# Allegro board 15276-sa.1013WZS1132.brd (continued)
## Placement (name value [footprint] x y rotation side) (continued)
PC4516  SCD1U16V2KX-3GP  [C402H22]  41 26.81 90 bottom
PC4521  SC18P50V2JN-1-GP  [C402H22]  42.4 58.3 0 top
PC4523  SCD1U50V3KX-L-GP  [C603H36]  34.02 47.64 90 top
PC4524  SCD1U50V3KX-L-GP  [C603H36]  39 50.3 0 top
PC4525  SCD1U50V3KX-L-GP  [C603H36]  45.19 47.25 270 top
PC4528  SC10U25V5KX-GP  [C805H56]  40.37 58.68 0 bottom
PC4529  SC10U25V5KX-GP  [C805H56]  40.55 50.05 0 top
PC4530  SC10U25V5KX-GP  [C805H56]  45.19 48.91 90 bottom
PC4601  SC1KP50V2KX-1GP  [C402H22]  124.8 143.98 180 top
PC4602  SC1U25V3KX-1-GP  [C603H36]  118.6 145.93 180 top
PC4603  SC3300P50V2KX-1GP  [C402H22]  124.75 139.43 180 bottom
PC4604  SCD1U10V2KX-4GP  [C402H20]  120 142.38 180 bottom
PC4605  SC1KP50V2KX-1GP  [C402H22]  113.14 143.83 270 top
PC4606  SC1KP50V2KX-1GP  [C402H22]  125.13 137.7 90 top
PC4607  SCD1U16V2KX-3GP  [C402H22]  122.46 145.04 0 top
PC4608  SC2D2U10V3KX-1GP  [C603H36]  119.03 133.11 0 top
PC4609  SCD01U50V2KX-1GP  [C402H22]  125.2 141.51 270 bottom
PC4610  SC330P50V2KX-3GP  [C402H22]  113.16 142.2 90 bottom
PC4611  SC2200P50V2KX-2GP  [C402H22]  113.49 140.93 0 bottom
PC4612  SC10P50V2JN-4GP  [C402H22]  113.22 139.69 270 bottom
PC4613  SC470P50V2KX-3GP  [C402H22]  113.82 137.09 270 bottom
PC4614  SCD01U50V2KX-1GP  [C402H22]  115.27 145.1 90 top
PC4615  SC100P50V2JN-3GP  [C402H22]  125.58 139 0 top
PC4616  SCD01U50V2KX-1GP  [C402H22]  113.04 142.17 90 top
PC4617  SC100P50V2JN-3GP  [C402H22]  112.55 136.61 180 bottom
PC4618  SC470P50V2KX-3GP  [C402H22]  124.75 139 0 top
PC4619  SCD1U16V2KX-3GP  [C402H22]  113.14 144.64 90 top
PC4622  SC1KP50V2KX-1GP  [C402H22]  113.82 137.78 270 top
PC4623  SCD047U25V2KX-GP  [C402H22]  114.28 136.54 180 top
PC4624  SC3300P50V2KX-1GP  [C402H22]  113.6 140.12 0 top
PC4626  SC2200P50V2KX-2GP  [C402H22]  126.27 141.06 90 top
PC4627  SC10P50V2JN-4GP  [C402H22]  124.75 140.68 0 top
PC4628  SCD047U25V2KX-GP  [C402H22]  125.13 136 90 top
PC4648  SC330P50V2KX-3GP  [C402H22]  126.7 142.33 0 top
PC4660  SC1KP50V2KX-1GP  [C402H22]  120.12 147.08 90 top
PC4713  SC10U25V5KX-GP  [C805H56]  110.73 130.31 90 top
PC4715  SC10U25V5KX-GP  [C805H56]  110.73 129.12 270 bottom
PC4716  SC10U25V5KX-GP  [C805H56]  126.85 130.31 90 bottom
PC4717  SC10U25V5KX-GP  [C805H56]  126.85 128.28 90 bottom
PC4718  SC10U25V5KX-GP  [C805H56]  126.85 132.22 270 top
PC4719  SC10U25V5KX-GP  [C805H56]  110.78 127.32 270 bottom
PC4720  SCD1U50V3KX-GP  [C603H36]  110.83 127.09 90 top
PC4721  SC10U25V5KX-GP  [C805H56]  126.85 130.31 270 top
PC4722  SCD1U50V3KX-GP  [C603H36]  126.85 126.58 90 bottom
PC4734  SCD22U25V3KX-GP  [C603H40]  120.43 133.11 0 bottom
PC4736  SCD22U25V3KX-GP  [C603H40]  117.63 133.11 0 bottom
PC4742  SC1KP50V2KX-1GP  [C402H22]  111.51 123.56 0 bottom
PC4743  SC1KP50V2KX-1GP  [C402H22]  126.47 124.72 0 bottom
PC4827  SCD1U50V3KX-GP  [C603H36]  154.67 103.52 270 bottom
PC4828  SC4D7U25V5KX-GP  [C805H54]  154.67 105.17 270 bottom
PC4829  SC1U10V2KX-1GP  [C402H22]  156.45 111.77 0 bottom
PC4830  SC10U25V5KX-GP  [C805H56]  154.67 107.07 270 bottom
PC4831  SC1KP50V2KX-1GP  [C402H22]  153.4 117.87 0 bottom
PC4832  SC18P50V2JN-1-GP  [C402H22]  156.06 117.87 180 bottom
PC4833  SCD1U50V3KX-GP  [C603H36]  153.4 109.48 180 bottom
PC4834  SCD1U10V2KX-4GP  [C402H20]  150.48 79.89 90 bottom
PC4838  SC560P50V-GP  [C603]  160.38 102.75 0 bottom
PC4901  SC1U10V3KX-3GP  [C603H36]  59.8 41.92 0 top
PC4902  SCD01U16V2KX-3GP  [C402H22]  56.62 46.24 270 top
PC4903  SCD1U10V2KX-4GP  [C402H20]  56.62 47.13 270 top
PC4904  SC1U10V3KX-3GP  [C603H36]  61.83 47.76 90 bottom
PC4906  SCD1U10V2KX-5GP  [C402H22]  65.88 44.85 90 top
PC4909  SC4D7U25V5KX-GP  [C805H54]  59.29 37.27 270 top
PC4911  SC4D7U25V5KX-GP  [C805H54]  59.29 35.47 270 top
PC4912  SC10U25V5KX-GP  [C805H56]  59.29 37.25 90 bottom
PC4913  SCD1U50V3KX-GP  [C603H36]  59.29 38.82 90 top
PC4914  SC4D7U25V5KX-GP  [C805H54]  59.29 35.44 90 bottom
PC4915  SCD1U10V2KX-4GP  [C402H20]  60.31 50.3 180 top
PC4916  SC10U6D3V3MX-GP  [C603H38]  61.45 50.56 180 top
PC4917  SC10U6D3V3MX-GP  [C603H38]  62.72 50.56 180 top
PC4918  SCD22U10V2KX-1GP  [C402H22]  59.42 50.3 180 top
PC4919  SCD1U50V3KX-GP  [C603H36]  61.45 41.54 180 top
PC4920  SC4D7U6D3V3KX-GP  [C603H36]  68.43 26.05 180 top
PC4921  SCD1U10V2KX-4GP  [C402H20]  69.58 18.3 0 top
PC4922  SC330P50V2KX-3GP  [C402H22]  58.94 33.56 180 top
PC4923  SC22U6D3V5MX-2GP  [C805H58]  66.78 25.92 180 top
PC4924  SC22U6D3V5MX-2GP  [C805H58]  64.88 25.92 180 top
PC4925  SC22U6D3V5MX-2GP  [C805H58]  64.88 18.3 0 top
PC4926  SC22U6D3V5MX-2GP  [C805H58]  66.78 18.3 0 top
PC5005  SC1U10V2KX-1GP  [C402H22]  49 61.99 180 bottom
PC5010  SC10U6D3V3MX-GP  [C603H38]  63.74 68.72 0 bottom
PC5011  SC10U6D3V3MX-GP  [C603H38]  49.89 68.97 0 bottom
PC5012  SC10U6D3V3MX-GP  [C603H38]  65.01 68.72 0 bottom
PC5013  SC1U6D3V2KX-GP  [C402H22]  47.23 64.53 180 bottom
PC5014  SC22P50V2JN-4GP  [C402H22]  46.21 62.75 180 top
PC5015  SC10U6D3V3MX-GP  [C603H38]  48.5 68.97 0 bottom
PC5020  SC680P50V2KX-2GP  [C402H22]  45.32 62.75 0 top
PD4201  P6SMB27A-GP  [DO214AAAKH97]  92.62 156.25 0 bottom
PD4203  LBAV99LT1G-1-GP  [SOT23-2D4-312H44]  78.98 168.67 0 top
PD4204  PESD24VS2UT-GP  [SOT-23-10H44]  85.45 173.24 0 top
PD4302  SMF18AT1G-GP  [SOD123FLAKH40]  156.57 172.35 90 top
PD4401  SD103AWS-1-GP  [SOD323AKH42]  133.08 153.05 270 bottom
PD4404  1N4148WS-7-F-GP  [SOD323AKH42]  117.15 157.74 270 top
PG4402  GAP-CLOSE-PWR-3-GP  [GAP-CLOSE-PWR-3]  118.85 173.11 90 top
PG4403  GAP-CLOSE-PWR-3-GP  [GAP-CLOSE-PWR-3]  120.63 173.11 90 top
PG4407  GAP-CLOSE-PWR-3-GP  [GAP-CLOSE-PWR-3]  123.43 155.48 180 top
PG4408  GAP-CLOSE-PWR-3-GP  [GAP-CLOSE-PWR-3]  123.43 156.4 180 top
PG4409  GAP-CLOSE-PWR-3-GP  [GAP-CLOSE-PWR-3]  159.37 162.44 180 bottom
PG4410  GAP-CLOSE-PWR-3-GP  [GAP-CLOSE-PWR-3]  159.37 163.97 180 bottom
PG4411  GAP-CLOSE-PWR-3-GP  [GAP-CLOSE-PWR-3]  126.6 154.32 180 bottom
PG4412  GAP-CLOSE-PWR-3-GP  [GAP-CLOSE-PWR-3]  140.95 159.65 270 bottom
PG4413  GAP-CLOSE-PWR-3-GP  [GAP-CLOSE-PWR-3]  140.19 159.65 270 bottom
PG4414  GAP-CLOSE-PWR-3-GP  [GAP-CLOSE-PWR-3]  139.43 159.65 270 bottom
PG4415  GAP-CLOSE-PWR-3-GP  [GAP-CLOSE-PWR-3]  138.67 159.65 270 bottom
PG4502  GAP-CLOSE-PWR-3-GP  [GAP-CLOSE-PWR-3]  30.46 50.94 90 top
PG4503  GAP-CLOSE-PWR-3-GP  [GAP-CLOSE-PWR-3]  31.22 50.94 90 top
PG4504  GAP-CLOSE-PWR-3-GP  [GAP-CLOSE-PWR-3]  31.99 50.94 90 top
PG4505  GAP-CLOSE-PWR-3-GP  [GAP-CLOSE-PWR-3]  32.87 50.94 90 top
PG4511  GAP-CLOSE-PWR-3-GP  [GAP-CLOSE-PWR-3]  47.23 26.43 90 bottom
PG4512  GAP-CLOSE-PWR-3-GP  [GAP-CLOSE-PWR-3]  46.46 26.43 90 bottom
PG4513  GAP-CLOSE-PWR-3-GP  [GAP-CLOSE-PWR-3]  30.46 26.68 270 bottom
PG4514  GAP-CLOSE-PWR-3-GP  [GAP-CLOSE-PWR-3]  47.99 26.43 90 bottom
PG4515  GAP-CLOSE-PWR-3-GP  [GAP-CLOSE-PWR-3]  50.15 47.51 0 top
PG4516  GAP-CLOSE-PWR-3-GP  [GAP-CLOSE-PWR-3]  50.15 48.27 0 top
PG4517  GAP-CLOSE-PWR-3-GP  [GAP-CLOSE-PWR-3]  50.15 49.03 0 top
PG4518  GAP-CLOSE-PWR-3-GP  [GAP-CLOSE-PWR-3]  50.15 49.79 0 top
PG4519  GAP-CLOSE-PWR-3-GP  [GAP-CLOSE-PWR-3]  50.15 50.56 0 top
PG4520  GAP-CLOSE-PWR-3-GP  [GAP-CLOSE-PWR-3]  50.15 51.32 0 top
PG4521  GAP-CLOSE-PWR-3-GP  [GAP-CLOSE-PWR-3]  50.15 52.08 0 top
PG4522  GAP-CLOSE-PWR-3-GP  [GAP-CLOSE-PWR-3]  31.22 26.68 270 bottom
PG4523  GAP-CLOSE-PWR-3-GP  [GAP-CLOSE-PWR-3]  31.99 26.68 270 bottom
PG4524  GAP-CLOSE-PWR-3-GP  [GAP-CLOSE-PWR-3]  43.42 26.43 90 bottom
PG4525  GAP-CLOSE-PWR-3-GP  [GAP-CLOSE-PWR-3]  32.75 26.68 270 bottom
PG4526  GAP-CLOSE-PWR-3-GP  [GAP-CLOSE-PWR-3]  33.51 26.68 270 bottom
PG4527  GAP-CLOSE-PWR-3-GP  [GAP-CLOSE-PWR-3]  42.65 26.43 90 bottom
PG4528  GAP-CLOSE-PWR-3-GP  [GAP-CLOSE-PWR-3]  44.18 26.43 90 bottom
PG4529  GAP-CLOSE-PWR-3-GP  [GAP-CLOSE-PWR-3]  44.94 26.43 90 bottom
PG4530  GAP-CLOSE-PWR-3-GP  [GAP-CLOSE-PWR-3]  34.27 26.68 270 bottom
PG4531  GAP-CLOSE-PWR-3-GP  [GAP-CLOSE-PWR-3]  45.7 26.43 90 bottom
PG4535  GAP-CLOSE-PWR-3-GP  [GAP-CLOSE-PWR-3]  48.75 26.43 90 bottom
PG4537  GAP-CLOSE-PWR-6-GP  [GAP-CLOSE-PWR]  27.79 27.95 180 bottom
PG4538  GAP-CLOSE-PWR-6-GP  [GAP-CLOSE-PWR]  41.76 57.92 270 bottom
PG4543  GAP-CLOSE-PWR-6-GP  [GAP-CLOSE-PWR]  41.92 50.68 270 top
PG4547  GAP-CLOSE-PWR-6-GP  [GAP-CLOSE-PWR]  50.15 27.95 0 bottom
PG4701  GAP-CLOSE-PWR-3-GP  [GAP-CLOSE-PWR-3]  111.36 114.31 90 bottom
PG4702  GAP-CLOSE-PWR-3-GP  [GAP-CLOSE-PWR-3]  111.36 112.02 270 bottom
PG4703  GAP-CLOSE-PWR-3-GP  [GAP-CLOSE-PWR-3]  103.26 122.11 180 bottom
PG4704  GAP-CLOSE-PWR-3-GP  [GAP-CLOSE-PWR-3]  103.26 122.87 180 bottom
PG4707  GAP-CLOSE-PWR-3-GP  [GAP-CLOSE-PWR-3]  103.26 125.16 180 bottom
PG4708  GAP-CLOSE-PWR-3-GP  [GAP-CLOSE-PWR-3]  103.26 125.92 180 bottom
PG4709  GAP-CLOSE-PWR-3-GP  [GAP-CLOSE-PWR-3]  103.26 124.39 180 bottom
PG4710  GAP-CLOSE-PWR-3-GP  [GAP-CLOSE-PWR-3]  103.26 123.63 180 bottom
PG4711  GAP-CLOSE-PWR-3-GP  [GAP-CLOSE-PWR-3]  132.57 131.71 0 top
PG4712  GAP-CLOSE-PWR-3-GP  [GAP-CLOSE-PWR-3]  132.57 130.95 0 top
PG4716  GAP-CLOSE-PWR-3-GP  [GAP-CLOSE-PWR-3]  132.57 130.19 0 top
PG4717  GAP-CLOSE-PWR-3-GP  [GAP-CLOSE-PWR-3]  132.57 133.23 0 top
PG4718  GAP-CLOSE-PWR-3-GP  [GAP-CLOSE-PWR-3]  132.57 132.47 0 top
PG4719  GAP-CLOSE-PWR-3-GP  [GAP-CLOSE-PWR-3]  123.55 111.77 270 bottom
PG4720  GAP-CLOSE-PWR-3-GP  [GAP-CLOSE-PWR-3]  123.55 114.06 90 bottom
PG4824  GAP-CLOSE-PWR-3-GP  [GAP-CLOSE-PWR-3]  150.48 82.81 0 bottom
PG4825  GAP-CLOSE-PWR-3-GP  [GAP-CLOSE-PWR-3]  150.48 83.58 0 bottom
PG4826  GAP-CLOSE-PWR-3-GP  [GAP-CLOSE-PWR-3]  150.48 84.34 0 bottom
PG4827  GAP-CLOSE-PWR-3-GP  [GAP-CLOSE-PWR-3]  148.7 108.98 90 top
PG4828  GAP-CLOSE-PWR-3-GP  [GAP-CLOSE-PWR-3]  150.48 85.1 0 bottom
PG4830  GAP-CLOSE-PWR-3-GP  [GAP-CLOSE-PWR-3]  150.48 81.29 0 bottom
PG4831  GAP-CLOSE-PWR-3-GP  [GAP-CLOSE-PWR-3]  150.48 82.05 0 bottom
PG4832  GAP-CLOSE-PWR-3-GP  [GAP-CLOSE-PWR-3]  150.48 86.24 0 bottom
PG4834  GAP-CLOSE-PWR-3-GP  [GAP-CLOSE-PWR-3]  147.17 108.98 90 top
PG4837  GAP-CLOSE-PWR-3-GP  [GAP-CLOSE-PWR-3]  149.46 108.98 90 top
PG4838  GAP-CLOSE-PWR-3-GP  [GAP-CLOSE-PWR-3]  147.94 108.98 90 top
PG4901  GAP-CLOSE-PWR-3-GP  [GAP-CLOSE-PWR-3]  65.64 51.19 180 top
PG4902  GAP-CLOSE-PWR-3-GP  [GAP-CLOSE-PWR-3]  65.64 50.43 180 top
PG4903  GAP-CLOSE-PWR-3-GP  [GAP-CLOSE-PWR-3]  66.53 38.49 90 top
PG4904  GAP-CLOSE-PWR-3-GP  [GAP-CLOSE-PWR-3]  65.64 38.49 90 top
PG4905  GAP-CLOSE-PWR-3-GP  [GAP-CLOSE-PWR-3]  64.75 38.49 90 top
PG4906  GAP-CLOSE-PWR-3-GP  [GAP-CLOSE-PWR-3]  67.42 38.49 90 top
PG4907  GAP-CLOSE-PWR-3-GP  [GAP-CLOSE-PWR-3]  60.43 19.19 0 top
PG4908  GAP-CLOSE-PWR-3-GP  [GAP-CLOSE-PWR-3]  70.72 23.51 180 top
PG4909  GAP-CLOSE-PWR-3-GP  [GAP-CLOSE-PWR-3]  70.72 22.74 180 top
PG4910  GAP-CLOSE-PWR-3-GP  [GAP-CLOSE-PWR-3]  70.72 21.98 180 top
PG4911  GAP-CLOSE-PWR-3-GP  [GAP-CLOSE-PWR-3]  70.72 25.03 180 top
PG4913  GAP-CLOSE-PWR-3-GP  [GAP-CLOSE-PWR-3]  70.72 18.93 180 top
PG4914  GAP-CLOSE-PWR-3-GP  [GAP-CLOSE-PWR-3]  70.72 19.7 180 top
PG4915  GAP-CLOSE-PWR-3-GP  [GAP-CLOSE-PWR-3]  70.72 20.46 180 top
PG4916  GAP-CLOSE-PWR-3-GP  [GAP-CLOSE-PWR-3]  70.72 21.22 180 top
PG4917  GAP-CLOSE-PWR-3-GP  [GAP-CLOSE-PWR-3]  70.72 24.27 180 top
PG4918  GAP-CLOSE-PWR-3-GP  [GAP-CLOSE-PWR-3]  70.72 25.79 180 top
PG4919  GAP-CLOSE-PWR-3-GP  [GAP-CLOSE-PWR-3]  70.72 26.55 180 top
PG5009  GAP-CLOSE-PWR-3-GP  [GAP-CLOSE-PWR-3]  45.83 68.72 0 bottom
PG5010  GAP-CLOSE-PWR-3-GP  [GAP-CLOSE-PWR-3]  66.4 66.81 0 bottom
PG5011  GAP-CLOSE-PWR-3-GP  [GAP-CLOSE-PWR-3]  66.4 66.05 0 bottom
PG5012  GAP-CLOSE-PWR-3-GP  [GAP-CLOSE-PWR-3]  66.4 65.29 0 bottom
PG5013  GAP-CLOSE-PWR-3-GP  [GAP-CLOSE-PWR-3]  66.4 64.53 0 bottom
PG5014  GAP-CLOSE-PWR-3-GP  [GAP-CLOSE-PWR-3]  45.83 67.96 0 bottom
PL4401  IND-5D6UH-45-GP-U  [L686647-127318H119]  155.94 157.36 270 bottom
PL4503  IND-2D2UH-122-GP-U  [L686647-127318H119]  44.3 39.63 180 bottom
PL4504  IND-2D2UH-122-GP-U  [L686647-127318H119]  34.14 39.76 0 bottom
PL4701  IND-D36UH-35-GP  [L7066-1830-UH158]  111.36 113.17 180 bottom
PL4702  IND-D36UH-35-GP  [L7066-1830-UH158]  123.55 112.91 180 bottom
PL4802  IND-2D2UH-46-GP-U1  [L7066-1830-UH119]  155.58 92.64 180 bottom
PL4902  COIL-D68UH-5-GP-U  [L7066-1830-UH119]  59.29 23.51 90 top
PL5002  IND-2D2UH-46-GP-U1  [L7066-1830-UH119]  58.15 66.05 270 bottom
PQ4201  FDV301N-NL-GP  [SOT23DGS2D4H44]  79.48 173.75 0 top
PQ4202  CH3904PT-GP  [SOT23CBE2D6H46]  83.04 168.67 180 top
PQ4203  2N7002KDW-GP  [SOT-363H44]  83.81 163.47 180 top
PQ4204  LMUN5212T1G-GP  [SOT323CBE2D2H40]  109.2 164.09 90 top
PQ4205  LMUN5112T1G-GP  [SOT323EBC2D2H40]  109.2 167.27 90 top
PQ4206  2N7002KDW-GP  [SOT-363H44]  103.36 162.04 90 bottom
PQ4208  2N7002K-2-GP  [SOT23DGS2D4H44]  79.57 161.59 180 top
PQ4402  2N7002KDW-GP  [SOT-363H44]  108.44 175.14 0 top
PQ4407  2N7002KDW-GP  [SOT-363H44]  124.26 162.39 90 bottom
PQ4408  2N7002KDW-GP  [SOT-363H44]  121.19 161.22 180 top
PQ4409  MMBT3906-4-GP  [SOT23CBE2D4H44]  117.28 160.67 90 top
PQ4410  2N7002KDW-GP  [SOT-363H44]  113.77 162.95 0 top
PR3622  10KR2J-3-GP  [R402H16]  154.16 77.73 180 bottom
PR4202  15KR2F-GP  [R402H16]  82.28 172.22 180 top
PR4203  10KR2J-3-GP  [R402H16]  78.72 176.16 270 top
PR4204  2K2R2J-2-GP  [R402H16]  76.56 169.05 180 top
PR4205  33R2J-2-GP  [R402H16]  79.36 171.33 270 top
PR4207  240KR3-GP  [R603H22]  98.03 159.8 270 bottom
PR4208  47KR3J-L-GP  [R603H22]  100.77 159.75 270 bottom
PR4209  100KR2J-1-GP  [R402H16]  83.17 172.22 0 top
PR4210  1KR2J-1-GP  [R402H16]  105.93 163.28 0 bottom
PR4211  10KR2J-3-GP  [R402H16]  85.83 163.08 180 top
PR4212  100KR2J-1-GP  [R402H16]  104.22 163.99 90 bottom
PR4213  100KR2J-1-GP  [R402H16]  102.45 163.99 90 bottom
PR4214  3K3R6J-GP  [R1206H28]  98.61 161.83 270 bottom
PR4215  1KR2J-1-GP  [R402H16]  80.37 164.48 180 top
PR4216  100KR2J-1-GP  [R402H16]  81.77 165.36 180 top
PR4217  0R0603-PAD-2-GP-U  [0R0603-PAD-1-U]  99.42 159.78 90 top
PR4218  100KR2J-1-GP  [R402H16]  81.77 161.81 0 top
PR4401  10KR2F-2-GP  [R402H16]  106.28 175.65 0 top
PR4402  D01R3721F-GP-U  [R3720H40]  119.74 170.95 90 top
PR4403  100KR2J-1-GP  [R402H16]  116.82 171.97 0 bottom
PR4404  3KR5J-GP  [R805H24]  111.49 174.38 270 top
PR4405  470KR2J-2-GP  [R402H16]  153.4 167.14 0 top
PR4406  0R2J-2-GP  [R402H16]  129.14 162.42 90 bottom
PR4407  309KR2F-GP  [R402H16]  123.83 158.33 90 top
PR4408  10R5J-GP  [R805H24]  134.47 159.27 0 top
PR4409  0R3J-0-U-GP  [R603H22]  133.71 154.57 90 top
PR4411  102KR2F-GP  [R402H16]  126.73 161.53 0 top
PR4412  3K3R2F-2-GP  [R402H16]  138.92 178.45 270 top
PR4413  84K5R2F-GP  [R402H16]  128.12 157.49 180 bottom
PR4414  3D3MR2J-GP  [R402H16]  127.74 160.13 270 top
PR4415  3K3R2F-2-GP  [R402H16]  137.14 178.45 90 top
PR4416  D01R3721F-GP-U  [R3720H40]  157.08 163.08 0 bottom
PR4417  100KR2J-1-GP  [R402H16]  124.34 153.63 90 top
PR4418  0R2J-2-GP  [R402H16]  125.38 152.31 180 top
PR4419  100KR2J-1-GP  [R402H16]  128.07 164.2 90 top
PR4420  7D5R2F-GP  [R402H16]  127.62 152.03 0 top
PR4421  10R2F-L-GP  [R402H14]  128.51 152.03 0 top
PR4422  0R0402-PAD-2-GP  [0R0402-PAD-1]  123.83 157.44 270 top
PR4423  59KR2F-GP  [R402H16]  124.34 154.52 270 top
PR4424  8K45R2F-2-GP  [R402H16]  126.88 155.28 270 bottom
PR4425  100KR2J-1-GP  [R402H16]  124.62 162.47 0 top
PR4426  0R0402-PAD-2-GP  [0R0402-PAD-1]  123.17 161.17 180 top
PR4427  66K5R2F-GP  [R402H16]  127.62 161.53 0 top
PR4428  100KR2J-1-GP  [R402H16]  130.28 163.31 180 top
PR4429  150KR2F-L-GP  [R402H16]  128.51 161.53 180 top
PR4430  100KR2J-1-GP  [R402H16]  130.28 161.53 0 top
PR4431  47KR2F-GP  [R402H16]  126.88 157.06 270 bottom
PR4432  120KR2F-L-GP  [R402H16]  129.52 160.13 90 top
PR4433  120KR2F-L-GP  [R402H16]  124.95 159.88 270 top
PR4434  100KR2J-1-GP  [R402H16]  125.61 162.47 0 top
PR4435  10KR2F-2-GP  [R402H16]  124.06 152.28 0 top
PR4436  120KR2F-L-GP  [R402H16]  129.39 164.3 180 top
PR4437  160KR2F-GP  [R402H16]  131.17 161.53 180 top
PR4438  100KR2J-1-GP  [R402H16]  129.39 161.53 180 top
PR4439  10KR2F-2-GP  [R402H16]  123.17 152.28 0 top
PR4464  680KR2J-GP  [R402H16]  113.9 158.89 270 top
PR4466  0R2J-2-GP  [R402H16]  115.81 163.46 180 top
PR4467  1MR2J-1-GP  [R402H16]  117.91 163.46 180 top
PR4468  0R2J-2-GP  [R402H16]  113.9 157.87 90 top
PR4469  100KR2J-1-GP  [R402H16]  118.8 163.46 0 top
PR4470  100KR2F-L1-GP  [R402H16]  115.63 165.24 270 top
PR4473  10KR2F-2-GP  [R402H16]  113.47 166.63 90 top
PR4475  0R2J-2-GP  [R402H16]  113.85 160.28 180 top
PR4476  0R2J-2-GP  [R402H16]  114.66 160.28 180 top
PR4505  1D5R3F-GP  [R603H22]  35.67 53.35 90 top
PR4506  0R2J-2-GP  [R402H16]  38.84 59.7 270 top
PR4507  110KR2F-GP  [R402H16]  36.68 58.43 180 top
PR4510  100KR2J-1-GP  [R402H16]  35.92 55.76 90 top
PR4511  287KR2F-GP  [R402H16]  44.18 58.3 180 top
PR4513  0R2J-2-GP  [R402H16]  42.02 59.57 90 top
PR4514  15KR2F-GP  [R402H16]  41.51 58.3 0 top
PR4516  6K65R2F-GP  [R402H16]  39.35 58.43 0 top
PR4518  10KR2F-2-GP  [R402H16]  37.57 58.43 180 top
PR4523  10KR2F-2-GP  [R402H16]  43.29 58.3 180 top
PR4524  1D5R3F-GP  [R603H22]  44.81 53.48 90 top
PR4526  0R2J-2-GP  [R402H16]  42.15 59.19 270 bottom
PR4527  0R2J-2-GP  [R402H16]  39.22 62.49 0 top
PR4528  0R2J-2-GP  [R402H16]  40.11 62.49 180 top
PR4529  0R2J-2-GP  [R402H16]  38.34 62.49 0 top
PR4530  0R2J-2-GP  [R402H16]  41.89 62.49 0 top
PR4531  0R2J-2-GP  [R402H16]  41 62.49 0 top
PR4601  0R2J-2-GP  [R402H16]  126.07 143.6 270 top
PR4602  100R2J-2-GP  [R402H14]  110.85 84.34 270 top
PR4603  0R2J-2-GP  [R402H16]  126.07 144.41 270 top
PR4604  100R2J-2-GP  [R402H14]  110.82 85.17 270 top
PR4605  NTC-100K-10-GP-U  [NTC-402H22-U]  116.19 108.85 90 bottom
PR4606  20KR2F-L-GP  [R402H16]  121.65 145.04 0 top
PR4607  0R0402-PAD-2-GP  [0R0402-PAD-1]  122.64 145.04 180 bottom
PR4608  300R2F-GP  [R402H16]  123.17 146.82 0 bottom
PR4609  0R0402-PAD-2-GP  [0R0402-PAD-1]  119.74 145.68 0 top
PR4610  2R2F-GP  [R402H16]  117.46 145.3 180 top
PR4611  54K9R2F-L-GP  [R402H16]  116.57 145.55 0 top
PR4612  1KR2F-3-GP  [R402H16]  115.27 145.93 90 top
PR4613  0R0402-PAD-2-GP  [0R0402-PAD-1]  113.14 144.74 90 bottom
PR4614  10KR2F-2-GP  [R402H16]  115.55 146.82 180 bottom
PR4615  10KR2F-2-GP  [R402H16]  116.44 146.82 180 bottom
PR4616  0R0402-PAD-2-GP  [0R0402-PAD-1]  117.33 146.82 0 bottom
PR4617  0R2J-2-GP  [R402H16]  114.66 146.82 0 bottom
PR4618  NTC-100K-10-GP-U  [NTC-402H22-U]  118.73 108.85 270 bottom
PR4619  20KR2F-L-GP  [R402H16]  113.14 145.45 90 top
PR4620  100R2J-2-GP  [R402H14]  110.82 86.31 270 top
PR4621  0R2J-2-GP  [R402H16]  113.16 143.01 90 top
PR4622  1KR2F-3-GP  [R402H16]  112.73 143.44 180 bottom
PR4623  49D9R2F-GP  [R402H16]  113.55 143.44 180 bottom
PR4624  8K2R2F-1-GP  [R402H16]  112.66 140.93 0 bottom
PR4625  26K1R2F-2-GP  [R402H16]  113.04 141.36 270 top
PR4626  22K6R2F-1-GP  [R402H16]  113.27 138.82 270 top
PR4627  1KR2F-3-GP  [R402H16]  112.76 140.12 0 top
PR4628  130KR2F-GP  [R402H16]  120.5 146.82 180 bottom
PR4629  75KR2F-GP  [R402H16]  113.42 138.34 0 bottom
PR4630  499KR2F-1-GP  [R402H16]  114.26 138.34 180 bottom
PR4631  5K49R2F-GP  [R402H16]  113.44 135.6 0 top
PR4632  10R2F-L-GP  [R402H14]  113.01 136.92 270 top
PR4633  69K8R3F-GP  [R603H22]  113.62 135.49 180 bottom
PR4634  130KR2F-GP  [R402H16]  122.28 146.82 180 bottom
PR4635  24KR2F-GP  [R402H16]  122.97 133.11 180 bottom
PR4636  10KR2F-2-GP  [R402H16]  123.83 133.11 180 bottom
PR4637  5K49R2F-GP  [R402H16]  125.2 136.46 270 bottom
PR4638  130KR2F-GP  [R402H16]  119.62 146.82 0 bottom
PR4639  10R2F-L-GP  [R402H14]  125.13 136.87 90 top
PR4640  30K1R2F-L-GP  [R402H16]  122.16 138.95 0 bottom
PR4641  1KR2F-3-GP  [R402H16]  125.58 139.43 180 bottom
PR4642  75KR2F-GP  [R402H16]  126.85 139.41 90 top
PR4643  499KR2F-1-GP  [R402H16]  126.85 138.57 270 top
PR4644  69K8R3F-GP  [R603H22]  125.18 137.53 270 bottom
PR4645  130KR2F-GP  [R402H16]  118.73 146.82 180 bottom
PR4646  26K1R2F-2-GP  [R402H16]  125.2 140.7 270 bottom
PR4647  8K2R2F-1-GP  [R402H16]  127.57 141.49 0 top
PR4648  130KR2F-GP  [R402H16]  121.39 146.82 0 bottom
PR4649  1KR2F-3-GP  [R402H16]  125.2 141.92 90 top
PR4650  49D9R2F-GP  [R402H16]  125.18 142.73 90 top
PR4651  0R2J-2-GP  [R402H16]  120.28 145.15 180 bottom
PR4652  0R2J-2-GP  [R402H16]  121.65 145.04 180 bottom
PR4653  0R2J-2-GP  [R402H16]  119.44 145.15 180 bottom
PR4660  1KR2F-3-GP  [R402H16]  114.28 134.83 0 top
PR4661  1KR2F-3-GP  [R402H16]  125.2 135.6 270 bottom
PR4677  NTC-220K-GP-U  [NTC-402H22-U]  119.01 110.42 180 bottom
PR4678  NTC-220K-GP-U  [NTC-402H22-U]  115.81 112.15 0 bottom
PR4701  2D2R3-1-U-GP  [R603H22]  116.24 133.11 180 bottom
PR4702  2D2R3-1-U-GP  [R603H22]  121.7 133.11 180 bottom
PR4709  2D2R6J-3-GP  [R1206H28]  111.46 120.48 0 bottom
PR4710  2D2R6J-3-GP  [R1206H28]  126.5 119.92 0 bottom
PR4817  150KR2F-L-GP  [R402H16]  151.49 117.87 180 bottom
PR4819  0R0402-PAD-2-GP  [0R0402-PAD-1]  152.38 117.87 180 bottom
PR4820  2D2R3-1-U-GP  [R603H22]  152 109.48 180 bottom
PR4821  0R0402-PAD-2-GP  [0R0402-PAD-1]  150.22 116.65 0 bottom
PR4822  11K8R2F-GP  [R402H16]  155.18 117.87 180 bottom
PR4823  33KR2F-2-GP  [R402H16]  154.29 117.87 0 bottom
PR4824  470KR2F-GP  [R402H16]  155.94 114.69 180 bottom
PR4835  10KR2J-3-GP  [R402H16]  150.2 114.9 0 bottom
PR4837  2D2R5F-2-GP  [R805H24]  160.38 98.94 0 bottom
PR4901  30K1R2F-L-GP  [R402H16]  56.62 45.35 270 top
PR4902  100KR2F-L1-GP  [R402H16]  65.89 46.62 90 top
PR4903  10KR2F-2-GP  [R402H16]  57.89 46.62 0 top
PR4904  20KR2F-L-GP  [R402H16]  65.89 48.4 270 top
PR4905  2D2R3-1-U-GP  [R603H22]  62.72 41.54 0 top
PR4906  0R0402-PAD-2-GP  [0R0402-PAD-1]  55.35 45.86 180 top
PR4907  0R0402-PAD-2-GP  [0R0402-PAD-1]  65.88 43.99 270 top
PR4908  12KR2F-L-GP  [R402H16]  65.89 47.51 90 top
PR4910  0R0402-PAD-2-GP  [0R0402-PAD-1]  65.89 45.73 90 top
PR4911  0R0603-PAD-2-GP-U  [0R0603-PAD-1-U]  58.27 50.43 180 top
PR4912  2D2R5F-2-GP  [R805H24]  59.42 31.25 180 top
PR5009  102KR2F-GP  [R402H16]  47.1 62.75 180 top
PR5010  0R0402-PAD-2-GP  [0R0402-PAD-1]  49.89 61.99 0 bottom
PR5011  100KR2F-L1-GP  [R402H16]  50.78 61.99 0 bottom
PR5012  2D2R2F-GP  [R402H16]  46.34 65.42 180 bottom
PR5013  51KR2F-L-GP  [R402H16]  47.99 62.75 0 top
PR5020  18KR2F-GP  [R402H16]  44.43 62.75 180 top
PT4701  SE330U2D5VM-14-GP  [SE361414H178]  102.72 107.07 90 bottom
PT4702  SE330U2VDM-L-GP  [CT7343H83]  101.2 114.39 90 bottom
PT4703  SE330U2VDM-L-GP  [CT7343H83]  138.64 118.65 270 bottom
PT4704  SE330U2D5VM-14-GP  [SE361414H178]  133.59 111.39 270 bottom
PT4705  SE33U25VM-10-GP  [SE361413H182]  59.04 56.65 90 bottom
PT4706  SE33U25VM-10-GP  [SE361413H182]  107.55 134.5 270 bottom
PT4803  SE330U2D5VM-14-GP  [SE361414H178]  156.48 83.4 270 bottom
PU4201  AON7401-GP  [PPAK-8P-3232H36]  110.6 171.08 270 top
PU4402  AON7401-GP  [PPAK-8P-3232H36]  114.41 171.08 90 top
PU4403  AON7401-GP  [PPAK-8P-3232H36]  157.18 168.74 270 top
PU4404  BQ24727RGRR-1-GP  [QFN20G3D5-G2D15H40]  128.79 156.17 0 top
PU4405  SIS412DN-T1-GE3-GP  [PPAK-8P-2H45]  147.1 158.53 270 bottom
PU4406  SIS412DN-T1-GE3-GP  [PPAK-8P-2H45]  148.62 153.96 90 bottom
PU4506  SIS412DN-T1-GE3-GP  [PPAK-8P-2H45]  36.18 43.19 180 top
PU4507  SIS780DN-T1-GE3-GP  [PPAK-8P-2H45]  42.27 43.17 180 top
PU4508  SIS412DN-T1-GE3-GP  [PPAK-8P-2H45]  46.84 44.71 0 top
PU4509  RT6575DGQW-GP  [QFN20-G1D75H32]  40.24 54.49 0 top
PU4510  SIS412DN-T1-GE3-GP  [PPAK-8P-2H45]  31.6 44.71 0 top
PU4601  NCP81128MNTXG-GP-U1  [LFQFN52J6-G4D8-1H40]  119.18 139.74 0 top
PU4701  SIRA14DP-T1-GE3-GP  [PPAK-5PH45]  107.22 123.33 180 bottom
PU4702  SIRA12DP-T1-GE3-GP  [PPAK-5PH45]  115.68 121.32 0 bottom
PU4703  SIRA14DP-T1-GE3-GP  [PPAK-5PH45]  107.22 123.33 0 top
PU4704  SIRA12DP-T1-GE3-GP  [PPAK-5PH45]  115.68 121.32 180 top
PU4706  SIRA12DP-T1-GE3-GP  [PPAK-5PH45]  122.16 120.79 180 top
PU4707  SIRA14DP-T1-GE3-GP  [PPAK-5PH45]  130.74 122.79 180 bottom
PU4708  SIRA12DP-T1-GE3-GP  [PPAK-5PH45]  122.16 120.79 0 bottom
PU4805  SIS412DN-T1-GE3-GP  [PPAK-8P-2H45]  157.21 99.32 0 bottom
PU4806  RT8237CZQW-2-GP  [DFN10G3-G265175H32]  152.89 113.8 180 bottom
PU4808  SIS412DN-T1-GE3-GP  [PPAK-8P-2H45]  152.76 100.85 180 bottom
PU4901  TPS51716RUKR-GP  [QFN20-G1D75H32]  61.45 46.24 0 top
PU4902  SIS412DN-T1-GE3-GP  [PPAK-8P-2H45]  62.59 32.65 0 top
PU4903  SIS412DN-T1-GE3-GP  [PPAK-8P-2H45]  56.24 31.13 180 top
PU5002  RT8068AZQWID-GP-U  [DFN10G3-G265175H32]  50.53 65.67 90 bottom
PWR1  ETY-CON4-34-GP  [6916K-Q04M-00L]  168.3 165.67 0 top
Q403  2N7002KDW-GP  [SOT-363H44]  85.83 80.66 90 bottom
Q601  2N7002KDW-GP  [SOT-363H44]  141.46 91.58 90 bottom
Q603  2N7002KDW-GP  [SOT-363H44]  138.02 95.19 270 bottom
Q701  2N7002K-2-GP  [SOT23DGS2D4H44]  133.59 98.82 270 top
Q2401  2N7002K-2-GP  [SOT23DGS2D4H44]  157.73 149.86 180 bottom
Q2402  DMP2130L-7-GP  [SOT23DGS2D4H48]  158.46 139.29 0 top
Q2403  2N7002K-2-GP  [SOT23DGS2D4H44]  154.79 139.33 0 top
Q2404  MMBT3906-4-GP  [SOT23CBE2D4H44]  156.83 133.36 270 top
Q2505  2N7002K-2-GP  [SOT23DGS2D4H44]  61.2 15.89 0 bottom
Q2601  2N7002KDW-GP  [SOT-363H44]  75.75 64.43 90 top
Q2602  2N7002K-2-GP  [SOT23DGS2D4H44]  80.86 57.97 180 top
Q2603  CH3904PT-GP  [SOT23CBE2D6H46]  75.55 49.92 0 top
Q3001  2N7002K-2-GP  [SOT23DGS2D4H44]  75.67 172.86 180 top
Q3002  CH3904PT-GP  [SOT23CBE2D6H46]  75.67 163.71 0 top
Q3003  CH3904PT-GP  [SOT23CBE2D6H46]  58.66 166.89 90 top
Q3004  DMP2130L-7-GP  [SOT23DGS2D4H48]  59.9 171.89 90 top
Q5401  LMBT3904LT1G-GP  [SOT23CBE2D4H44]  29.32 79.28 270 top
Q5402  2N7002KDW-GP  [SOT-363H44]  25 79.72 90 bottom
Q5403  2N7002K-2-GP  [SOT23DGS2D4H44]  25.25 78.37 180 top
Q5502  2N7002KDW-GP  [SOT-363H44]  30.23 64.72 90 bottom
Q6103  RN2418-GP  [SOT23CBE2D6H62]  43.29 12.66 270 top
Q6104  RN2418-GP  [SOT23CBE2D6H62]  43.29 8.65 180 top
Q6105  2N7002K-2-GP  [SOT23DGS2D4H44]  35.29 10.17 0 top
Q6106  RN2418-GP  [SOT23CBE2D6H62]  31.48 10.3 180 top
Q6107  2N7002K-2-GP  [SOT23DGS2D4H44]  38.97 10.3 180 top
Q6201  RN2418-GP  [SOT23CBE2D6H62]  161.96 114.26 0 bottom
Q6202  2N7002KDW-GP  [SOT-363H44]  53.83 74.81 180 top
Q6203  P8503BMG-GP  [SOT23DGS2D8H56]  162.06 131.25 90 top
Q6204  DMP2130L-7-GP  [SOT23DGS2D4H48]  166.89 149.45 270 bottom
Q6205  2N7002K-2-GP  [SOT23DGS2D4H44]  166.73 153.17 180 bottom
R301  1KR2F-3-GP  [R402H16]  116.85 93.89 0 top
R302  1K69R2F-2-GP  [R402H16]  117.69 93.89 0 top
R401  150R2F-1-GP  [R402H16]  99.7 92.26 90 top
R402  2KR2F-3-GP  [R402H16]  100.11 88.33 90 bottom
R403  1KR2J-1-GP  [R402H16]  88.91 79.23 0 top
R404  0R0402-PAD-2-GP  [0R0402-PAD-1]  100.11 89.19 90 bottom
R405  150R2F-1-GP  [R402H16]  100.06 93.82 90 bottom
R406  150R2F-1-GP  [R402H16]  100 92.88 90 bottom
R407  499R2F-2-GP  [R402H16]  100 91.1 90 bottom
R408  150R2F-1-GP  [R402H16]  100 91.99 90 bottom
R409  0R2J-2-GP  [R402H16]  89.58 84.92 270 bottom
R410  1KR2J-1-GP  [R402H16]  100.06 82.27 90 bottom
R411  1KR2J-1-GP  [R402H16]  100.06 84.05 90 bottom
R412  0R0402-PAD-2-GP  [0R0402-PAD-1]  100.08 87.49 270 bottom
R413  1KR2J-1-GP  [R402H16]  100.06 83.16 90 bottom
R414  0R2J-2-GP  [R402H16]  95.73 95.2 90 bottom
R415  1KR2J-1-GP  [R402H16]  100.06 80.49 90 bottom
R416  1KR2J-1-GP  [R402H16]  100.06 81.38 90 bottom
R417  0R0402-PAD-2-GP  [0R0402-PAD-1]  107.04 82.33 90 top
R418  0R0402-PAD-2-GP  [0R0402-PAD-1]  95.36 96.53 180 bottom
R419  511R2F-2-GP  [R402H16]  100.08 86.65 90 bottom
R420  511R2F-2-GP  [R402H16]  100.06 85.82 90 bottom
R421  300R2J-4-GP  [R402H16]  89.58 84.03 270 bottom
R422  1KR2J-1-GP  [R402H16]  94.72 86.24 0 top
R423  1KR2J-1-GP  [R402H16]  95.61 86.88 180 top
R424  1KR2J-1-GP  [R402H16]  93.83 85.35 180 top
R425  1KR2J-1-GP  [R402H16]  92.06 84.97 270 top
R426  1KR2J-1-GP  [R402H16]  88.18 77.86 90 top
R429  1KR2J-1-GP  [R402H16]  28.3 71.26 0 top
R434  1KR2J-1-GP  [R402H16]  100.06 84.93 270 bottom
R503  39D2R2F-L-GP  [R402H16]  120.22 75.51 0 top
R504  1KR2J-1-GP  [R402H16]  118.42 78.94 90 top
R601  10KR2J-3-GP  [R402H16]  133.07 80.43 270 bottom
R602  0R2J-2-GP  [R402H16]  132.95 95.9 90 bottom
R603  10KR2J-3-GP  [R402H16]  134.8 80.43 90 bottom
R604  10KR2J-3-GP  [R402H16]  133.07 81.32 270 bottom
R608  10KR2J-3-GP  [R402H16]  144.25 95.26 270 bottom
R609  0R2J-2-GP  [R402H16]  139.93 88.71 180 bottom
R611  0R2J-2-GP  [R402H16]  137.13 88.59 180 bottom
R612  0R2J-2-GP  [R402H16]  128.58 103.26 180 bottom
R613  0R2J-2-GP  [R402H16]  127.74 103.26 180 bottom
R614  0R2J-2-GP  [R402H16]  126.9 103.26 180 bottom
R616  33R2J-2-GP  [R402H16]  129.42 103.26 0 bottom
R617  10KR2J-3-GP  [R402H16]  137.38 84.59 270 bottom
R618  0R2J-2-GP  [R402H16]  133.07 91.51 90 bottom
R620  10KR2J-3-GP  [R402H16]  132.49 95.82 90 top
R621  10KR2J-3-GP  [R402H16]  125.89 88.36 0 top
R622  0R2J-2-GP  [R402H16]  134.09 89.09 90 bottom
R623  20MR3-GP  [R603H22]  124.62 103.47 270 bottom
R625  0R2J-2-GP  [R402H16]  133.07 93.29 90 bottom
R626  100KR2J-1-GP  [R402H16]  134.09 88.25 270 bottom
R627  10KR2J-3-GP  [R402H16]  136.29 88.59 0 bottom
R628  1KR2J-1-GP  [R402H16]  139.2 92.44 90 top
R629  100KR2J-1-GP  [R402H16]  139.2 91.58 90 top
R630  10KR2J-3-GP  [R402H16]  133.07 92.4 270 bottom
R631  10KR2J-3-GP  [R402H16]  136 102.75 270 bottom
R632  10KR2J-3-GP  [R402H16]  126.73 83.7 90 top
R633  10KR2J-3-GP  [R402H16]  122.79 100.85 0 bottom
R634  10KR2J-3-GP  [R402H16]  133.85 87.41 270 bottom
R635  10KR2J-3-GP  [R402H16]  134.8 81.32 90 bottom
R637  10KR2J-3-GP  [R402H16]  136 101.86 270 bottom
R638  10KR2J-3-GP  [R402H16]  135.36 83.2 0 bottom
R639  10KR2J-3-GP  [R402H16]  133.58 85.54 270 bottom
R640  10KR2J-3-GP  [R402H16]  133.58 84.65 90 bottom
R641  10KR2J-3-GP  [R402H16]  136.63 83.2 270 bottom
R642  100KR2J-1-GP  [R402H16]  133.58 83.25 0 bottom
R643  100KR2J-1-GP  [R402H16]  134.47 83.25 180 bottom
R644  10KR2J-3-GP  [R402H16]  132.49 96.63 90 top
R645  15KR2J-1-GP  [R402H16]  133.2 94.43 90 bottom
R646  15KR2J-1-GP  [R402H16]  133.07 90.62 90 bottom
R647  15KR2J-1-GP  [R402H16]  136.05 91.32 270 top
R648  100KR2J-1-GP  [R402H16]  146.69 93.9 180 bottom
R649  10KR2J-3-GP  [R402H16]  135.74 94.94 0 bottom
R650  10KR2J-3-GP  [R402H16]  145.24 92.92 0 top
R651  10KR2J-3-GP  [R402H16]  132.11 104.66 90 top
R701  10KR2J-3-GP  [R402H16]  136.22 95.49 270 top
R702  10KR2J-3-GP  [R402H16]  131.3 98.44 0 top
R703  0R3J-0-U-GP  [R603H22]  122.79 86.24 0 top
R1301  4K7R2J-2-GP  [R402H16]  142.73 28.08 180 top
R1901  0R2J-2-GP  [R402H16]  130.26 103.26 180 bottom
R1902  11K8R2F-GP  [R402H16]  127.24 101.61 0 top
R1903  1KR2F-3-GP  [R402H16]  126.43 85.93 180 top
R1904  1KR2F-3-GP  [R402H16]  123.86 85.96 180 top
R1905  1MR2J-1-GP  [R402H16]  110.93 100.16 270 bottom
R1906  0R2J-2-GP  [R402H16]  133.97 98.44 90 bottom
R1907  0R2J-2-GP  [R402H16]  137.16 105.14 0 bottom
R1908  0R2J-2-GP  [R402H16]  137.65 101.48 90 top
R1909  1KR2F-3-GP  [R402H16]  121.64 92.25 90 top
R1910  1KR2F-3-GP  [R402H16]  119.62 90.43 0 top
R1911  10KR2J-L-GP  [R402H15]  133.96 99.38 90 bottom
R1912  2KR2J-1-GP  [R402H16]  136.27 105.14 0 bottom
R1913  10KR2J-3-GP  [R402H16]  146.54 144.28 90 top
R1914  2KR2J-1-GP  [R402H16]  133.97 107.07 90 bottom
R1915  10KR2J-L-GP  [R402H15]  137.26 90.62 180 bottom
R1916  2KR2J-1-GP  [R402H16]  138.15 89.48 180 bottom
R1917  2KR2J-1-GP  [R402H16]  138.6 87.51 90 bottom
R1918  10KR2J-3-GP  [R402H16]  139.04 89.48 0 bottom
R1919  2KR2J-1-GP  [R402H16]  132.69 98.62 180 bottom
R1920  10KR2J-3-GP  [R402H16]  136.73 103.87 90 bottom
R1921  0R2J-2-GP  [R402H16]  137.65 102.37 90 top
R1922  0R2J-2-GP  [R402H16]  137.65 103.26 90 top
R1923  0R2J-2-GP  [R402H16]  138.03 98.11 0 bottom
R1924  0R2J-2-GP  [R402H16]  137.17 98.08 0 bottom
R1925  33R2J-2-GP  [R402H16]  137.7 100.26 90 top
R1926  2KR2J-1-GP  [R402H16]  135.74 92.91 180 bottom
R1927  10KR2J-L-GP  [R402H15]  134.85 92.91 180 bottom
R1928  2KR2J-1-GP  [R402H16]  139.38 85.95 180 bottom
R1929  10KR2J-L-GP  [R402H15]  138.49 85.95 180 bottom
R1930  0R2J-2-GP  [R402H16]  112.17 100.59 180 bottom
R1931  10KR2J-3-GP  [R402H16]  138.54 79.58 180 bottom
R2401  10KR2J-3-GP  [R402H16]  149.46 143.62 270 top
R2402  0R0603-PAD-2-GP-U  [0R0603-PAD-1-U]  151.87 123.71 270 top
R2403  2D2R3-1-U-GP  [R603H22]  145.52 124.47 0 top
R2404  10KR2F-2-GP  [R402H16]  144.38 130.57 180 bottom
R2405  27KR2F-L-GP  [R402H16]  142.85 136.19 270 bottom
R2406  100KR2F-L1-GP  [R402H16]  142.22 130.06 270 top
R2407  100KR2F-L1-GP  [R402H16]  142.92 133.57 90 bottom
R2408  0R2J-2-GP  [R402H16]  159.75 144.92 90 top
R2409  0R2J-2-GP  [R402H16]  149.84 146.7 0 top
R2410  0R2J-2-GP  [R402H16]  148.7 139.08 270 top
R2411  0R2J-2-GP  [R402H16]  144.63 144.28 270 top
R2412  10KR2J-3-GP  [R402H16]  143.39 138.95 90 bottom
R2413  100KR2J-1-GP  [R402H16]  157.95 123.63 90 bottom
R2414  10KR2J-3-GP  [R402H16]  153.91 124.06 270 top
R2415  10KR2J-3-GP  [R402H16]  161.68 147.03 0 bottom
R2416  0R2J-2-GP  [R402H16]  150.4 139.43 90 top
R2417  0R0402-PAD-2-GP  [0R0402-PAD-1]  157.79 146.77 90 top
R2418  10KR2J-3-GP  [R402H16]  153.03 123.91 270 bottom
R2419  0R2J-2-GP  [R402H16]  148.32 122.24 180 bottom
R2420  33R2J-2-GP  [R402H16]  149.82 124.39 270 top
R2421  100KR2J-1-GP  [R402H16]  155.05 146.82 0 bottom
R2422  0R2J-2-GP  [R402H16]  150.58 123.84 180 bottom
R2423  0R2J-2-GP  [R402H16]  151.48 123.85 180 bottom
R2424  0R2J-2-GP  [R402H16]  153.02 123.07 90 bottom
R2425  330KR2J-L1-GP  [R402H16]  148.32 130.44 180 top
R2426  100KR2J-1-GP  [R402H16]  161.07 124.62 0 top
R2427  0R0402-PAD-2-GP  [0R0402-PAD-1]  149.21 130.44 0 top
R2428  0R0402-PAD-2-GP  [0R0402-PAD-1]  151.11 137.3 90 top
R2429  100KR2J-1-GP  [R402H16]  150.1 130.44 180 top
R2430  0R0402-PAD-2-GP  [0R0402-PAD-1]  157.92 124.47 90 bottom
R2431  330KR2J-L1-GP  [R402H16]  154.41 135.39 180 top
R2432  1KR2J-1-GP  [R402H16]  153.52 134.63 180 top
R2433  20KR2F-L-GP  [R402H16]  153.52 136.41 180 top
R2434  0R2J-2-GP  [R402H16]  144.43 124.57 180 top
R2435  0R0402-PAD-2-GP  [0R0402-PAD-1]  141.46 135.01 0 bottom
R2436  10KR2J-3-GP  [R402H16]  152.15 140.8 180 top
R2437  100KR2J-1-GP  [R402H16]  154.29 121.8 0 top
R2438  0R0402-PAD-2-GP  [0R0402-PAD-1]  157.44 147.1 0 bottom
R2439  10KR2J-3-GP  [R402H16]  156.06 135.65 270 top
R2440  0R2J-2-GP  [R402H16]  160.38 151.27 270 bottom
R2441  10KR2J-3-GP  [R402H16]  143.36 140.6 90 bottom
R2442  100KR2J-1-GP  [R402H16]  156.57 147.1 0 bottom
R2443  10KR2J-3-GP  [R402H16]  147.15 145.4 270 bottom
R2444  0R2J-2-GP  [R402H16]  152 146.82 0 top
R2445  100KR2J-1-GP  [R402H16]  151.11 146.82 180 top
R2446  32K4R2F-1-GP  [R402H16]  142.85 135.37 270 bottom
R2447  1KR2J-1-GP  [R402H16]  160.13 127.01 270 top
R2448  0R2J-2-GP  [R402H16]  152.13 130.95 90 top
R2449  10KR2F-2-GP  [R402H16]  147.86 123.56 270 bottom
R2450  0R2J-2-GP  [R402H16]  147.94 123.84 180 top
R2451  13K7R2F-GP  [R402H16]  147.86 124.39 270 bottom
R2452  1KR2J-1-GP  [R402H16]  164.14 143.75 90 bottom
R2453  1KR2J-1-GP  [R402H16]  165.82 143.75 270 bottom
R2454  0R2J-2-GP  [R402H16]  154.92 143.65 180 top
R2501  10KR2J-3-GP  [R402H16]  144.76 101.23 0 top
R2502  1KR2J-1-GP  [R402H16]  58.47 15.47 90 bottom
R2504  10MR2J-L-GP  [R402H16]  58.47 14.58 90 bottom
R2601  0R2J-2-GP  [R402H16]  78.59 58.99 180 top
R2602  0R2J-2-GP  [R402H16]  148.37 133.61 90 top
R2603  18K7R2F-GP  [R402H16]  78.16 62.77 0 top
R2604  2KR2F-3-GP  [R402H16]  78.59 56.07 180 top
R2605  0R2J-2-GP  [R402H16]  89.26 160.03 90 bottom
R2606  0R2J-2-GP  [R402H16]  95.87 150 180 bottom
R2607  0R3J-0-U-GP  [R603H22]  148.32 135.52 180 top
R2610  NTC-100K-8-GP  [NTC-603H38]  142.35 97.17 0 top
R2611  24K3R2F-1-GP  [R402H16]  150.05 133.61 90 top
R2612  0R2J-2-GP  [R402H16]  152.59 132.45 180 top
R2622  24K3R2F-1-GP  [R402H16]  153.91 131.33 90 top
R2624  2KR2F-3-GP  [R402H16]  146.64 133.61 90 top
R2701  0R2J-2-GP  [R402H16]  161.02 8.01 180 top
R2702  0R5J-5-GP  [R805H24]  147.89 10.1 90 top
R2703  0R3J-0-U-GP  [R603H22]  164.07 17.41 270 top
R2704  0R5J-5-GP  [R805H24]  147.94 8.14 90 top
R2705  0R2J-2-GP  [R402H16]  151.49 16.65 270 top
R2706  0R0805-PAD-2-GP-U  [0R0805-PAD-1-U]  164.07 4.96 90 top
R2707  20KR2F-L-GP  [R402H16]  154.67 18.43 0 bottom
R2708  0R0402-PAD-2-GP  [0R0402-PAD-1]  151.11 6.23 270 bottom
R2709  200KR2F-L-GP  [R402H16]  153.78 18.43 0 bottom
R2711  100KR2J-1-GP  [R402H16]  163.05 14.87 270 top
R2712  0R2J-2-GP  [R402H16]  157.41 25.03 180 top
R2714  0R2J-2-GP  [R402H16]  101.45 141.49 270 bottom
R2716  0R2J-2-GP  [R402H16]  101.45 142.38 270 bottom
R2717  1KR2J-1-GP  [R402H16]  153.55 22.79 270 top
R2718  0R2J-2-GP  [R402H16]  151.49 15.76 90 top
R2719  0R2J-2-GP  [R402H16]  149.59 16.97 180 bottom
R2720  0R2J-2-GP  [R402H16]  150.48 13.41 180 bottom
R2721  0R2J-2-GP  [R402H16]  155.35 28.79 180 bottom
R2722  100KR2J-1-GP  [R402H16]  152.89 18.43 180 bottom
R2723  0R2J-2-GP  [R402H16]  154.52 28.79 180 bottom
R2901  0R3J-0-U-GP  [R603H22]  62.21 11.82 90 bottom
R2902  0R3J-0-U-GP  [R603H22]  62.21 9.92 90 bottom
R2903  0R3J-0-U-GP  [R603H22]  62.08 7.38 90 bottom
R2904  0R3J-0-U-GP  [R603H22]  62.08 5.34 90 bottom
R2906  0R3J-0-U-GP  [R603H22]  161.91 22.49 270 top
R2907  0R3J-0-U-GP  [R603H22]  160.51 26.81 270 top
R2908  10R2F-L-GP  [R402H14]  163.23 10.42 90 top
R2909  0R3J-0-U-GP  [R603H22]  161.91 25.28 270 top
R2910  10R2F-L-GP  [R402H14]  163.23 9.54 90 top
R2911  0R3J-0-U-GP  [R603H22]  161.91 23.89 270 top
R2912  4K7R2J-2-GP  [R402H16]  163.23 11.31 90 top
R2913  4K7R2J-2-GP  [R402H16]  163.23 12.2 90 top
R2919  10KR2J-3-GP  [R402H16]  165.46 8.65 0 top
R2920  10KR2J-3-GP  [R402H16]  165.08 6.49 90 top
R2921  1KR2J-1-GP  [R402H16]  158.86 20.97 0 bottom
R2922  1KR2J-1-GP  [R402H16]  160.76 20.97 0 bottom
R2923  0R3J-0-U-GP  [R603H22]  161.91 21.09 90 top
R3001  0R3J-0-U-GP  [R603H22]  56.79 175.15 180 top
R3002  0R2J-2-GP  [R402H16]  49.03 173.37 270 top
R3003  10KR2J-3-GP  [R402H16]  74.4 160.39 270 top
R3004  10KR2J-3-GP  [R402H16]  76.89 160.39 90 top
R3005  0R0402-PAD-2-GP  [0R0402-PAD-1]  75.8 166.13 90 top
R3006  0R3J-0-U-GP  [R603H22]  57.39 170.83 180 top
R3014  1KR2J-1-GP  [R402H16]  55.1 168.26 270 top
R3015  15KR2J-1-GP  [R402H16]  55.1 167.4 90 top
R3016  0R0603-PAD-2-GP-U  [0R0603-PAD-1-U]  61.96 166 270 top
R3021  10KR2J-3-GP  [R402H16]  75.67 169.05 180 top
R3022  20KR2J-L2-GP  [R402H16]  63.1 171.46 180 top
R3023  100KR2J-1-GP  [R402H16]  76.44 175.27 270 top
R3032  2K49R2F-GP  [R402H16]  47.4 173.77 0 top
R3033  10KR2J-3-GP  [R402H16]  55.65 169.08 90 top
R3201  0R2J-2-GP  [R402H16]  22.97 20.46 270 bottom
R3202  0R2J-2-GP  [R402H16]  17 24.27 270 bottom
R3203  6K2R2F-GP  [R402H16]  15.86 14.62 180 bottom
R3204  0R2J-2-GP  [R402H16]  14.46 17.66 0 bottom
R3205  0R2J-2-GP  [R402H16]  13.57 17.66 0 bottom
R3301  -  [0R0402-PAD]  29.06 25.92 270 top
R3401  0R2J-2-GP  [R402H16]  22.03 36.51 270 top
R3402  0R2J-2-GP  [R402H16]  22.03 35.7 270 top
R3408  0R2J-2-GP  [R402H16]  25.13 41.18 90 bottom
R3409  0R2J-2-GP  [R402H16]  25.13 40.37 90 bottom
R3410  0R2J-2-GP  [R402H16]  25.38 39.03 90 bottom
R3411  0R2J-2-GP  [R402H16]  25.38 38.21 90 bottom
R3412  0R2J-2-GP  [R402H16]  154.54 44.94 270 bottom
R3413  0R2J-2-GP  [R402H16]  154.54 45.76 270 bottom
R3414  0R2J-2-GP  [R402H16]  154.54 41.82 270 bottom
R3415  0R2J-2-GP  [R402H16]  154.54 41.01 270 bottom
R3501  100KR2J-1-GP  [R402H16]  18.75 43.11 0 top
R3602  200KR2J-L1-GP  [R402H16]  157.46 143.14 270 top
R3603  1KR2J-1-GP  [R402H16]  157.54 141.78 270 top
R3604  0R2J-2-GP  [R402H16]  155.05 77.73 0 bottom
R3605  0R2J-2-GP  [R402H16]  155.94 77.73 0 bottom
R3609  0R2J-2-GP  [R402H16]  38.59 22.24 180 top
R3624  1KR2J-1-GP  [R402H16]  150.93 77.15 90 bottom
R3625  100KR2J-1-GP  [R402H16]  150.35 21.6 270 top
R3626  100KR2J-1-GP  [R402H16]  150.35 22.49 90 top
R3627  0R2J-2-GP  [R402H16]  156.7 75.93 0 bottom
R5201  0R0402-PAD-2-GP  [0R0402-PAD-1]  92.31 144.03 90 bottom
R5202  100KR2J-1-GP  [R402H16]  104.6 155.94 270 top
R5203  0R2J-2-GP  [R402H16]  98.53 139.46 90 top
R5204  0R2J-2-GP  [R402H16]  98.53 138.57 90 top
R5205  0R2J-2-GP  [R402H16]  98.53 136.79 90 top
R5206  0R2J-2-GP  [R402H16]  103.87 147.46 0 bottom
R5207  0R2J-2-GP  [R402H16]  97.64 141.21 90 top
R5208  10KR2J-3-GP  [R402H16]  97.21 144.74 0 bottom
R5209  0R2J-2-GP  [R402H16]  96.37 144.74 180 bottom
R5210  100R2J-2-GP  [R402H14]  97.77 147.97 180 bottom
R5211  0R5J-5-GP  [R805H24]  99.98 154.52 90 top
R5212  0R2J-2-GP  [R402H16]  97.64 142.02 90 top
R5222  0R2J-2-GP  [R402H16]  102.98 147.46 0 bottom
R5229  0R3J-0-U-GP  [R603H22]  90.89 141.82 270 bottom
R5230  0R0603-PAD-2-GP-U  [0R0603-PAD-1-U]  88.75 139.96 180 bottom
R5231  0R3J-0-U-GP  [R603H22]  90.02 139.96 180 bottom
R5232  0R3J-0-U-GP  [R603H22]  95.87 138.06 0 bottom
R5233  100R2J-2-GP  [R402H14]  100.44 150.38 0 top
R5401  0R2J-2-GP  [R402H16]  19.79 75.32 90 bottom
R5402  0R2J-2-GP  [R402H16]  19.79 74.43 90 bottom
R5403  0R2J-2-GP  [R402H16]  19.79 77.1 90 bottom
R5404  0R2J-2-GP  [R402H16]  19.79 76.21 90 bottom
R5405  0R2J-2-GP  [R402H16]  19.88 69.45 180 bottom
R5406  0R2J-2-GP  [R402H16]  20.89 69.45 180 bottom
R5407  0R2J-2-GP  [R402H16]  19.79 73.42 90 bottom
R5408  0R2J-2-GP  [R402H16]  19.79 72.53 90 bottom
R5410  200KR2F-L-GP  [R402H16]  17.08 79.97 270 bottom
R5411  150KR2F-L-GP  [R402H16]  17.08 79.08 270 bottom
R5412  100KR2J-1-GP  [R402H16]  31.1 75.32 0 top
R5413  100KR2J-1-GP  [R402H16]  45.24 16.72 90 top
R5414  150R2J-L1-GP-U  [R402H16]  18.4 74.81 180 bottom
R5415  150R2J-L1-GP-U  [R402H16]  20.3 68.08 270 bottom
R5416  150R2J-L1-GP-U  [R402H16]  18.4 76.59 180 bottom
R5417  150R2J-L1-GP-U  [R402H16]  18.4 72.91 180 bottom
R5418  0R2J-2-GP  [R402H16]  22.46 78.12 90 top
R5419  0R2J-2-GP  [R402H16]  30.28 75.32 180 top
R5448  0R2J-2-GP  [R402H16]  98.53 135.01 90 top
R5449  0R2J-2-GP  [R402H16]  133.08 79.61 90 bottom
R5506  0R3J-0-U-GP  [R603H22]  27.54 75.83 270 top
R5523  150R2F-1-GP  [R402H16]  25.76 64.02 0 top
R5524  150R2F-1-GP  [R402H16]  25.76 61.22 0 top
R5525  150R2F-1-GP  [R402H16]  25.76 58.3 180 top
R5526  33R2J-L1-GP  [R402H15]  28.91 64.63 270 top
R5527  33R2J-L1-GP  [R402H15]  28.91 65.44 270 top
R5601  0R5J-5-GP  [R805H24]  162.16 38.62 270 bottom
R5602  0R2J-2-GP  [R402H16]  163.3 84.87 270 top
R5603  0R5J-5-GP  [R805H24]  170.16 85.1 0 bottom
R5604  10KR2J-3-GP  [R402H16]  164.07 80.53 0 top
R5605  0R2J-2-GP  [R402H16]  163.81 32.01 270 bottom
R5610  100KR2J-1-GP  [R402H16]  163.61 81.8 270 top
R5801  0R2J-2-GP  [R402H16]  160.08 66.91 0 bottom
R5802  0R2J-2-GP  [R402H16]  160.89 66.91 0 bottom
R5803  0R2J-2-GP  [R402H16]  163.18 53.22 180 top
R5804  0R2J-2-GP  [R402H16]  165.21 53.99 0 top
R5805  0R2J-2-GP  [R402H16]  166.1 53.99 0 top
R5806  0R2J-2-GP  [R402H16]  167.88 53.99 0 top
R5807  0R2J-2-GP  [R402H16]  166.99 53.99 0 top
R5808  0R2J-2-GP  [R402H16]  159.11 52.59 90 bottom
R5809  0R5J-5-GP  [R805H24]  167.9 66.18 270 bottom
R5810  0R2J-2-GP  [R402H16]  170.8 66.3 180 bottom
R5811  0R2J-2-GP  [R402H16]  159.15 53.52 90 bottom
R5812  10KR2J-3-GP  [R402H16]  162.29 54.37 180 top
R6101  330R2J-3-GP  [R402H16]  46.21 5.47 180 top
R6102  100R2J-2-GP  [R402H14]  167.7 162.39 0 bottom
R6103  499R2F-2-GP  [R402H16]  44.05 5.09 90 top
R6104  0R2J-2-GP  [R402H16]  45.7 9.92 180 top
R6105  0R2J-2-GP  [R402H16]  45.83 13.47 0 top
R6106  0R2J-2-GP  [R402H16]  36.3 7.25 0 top
R6108  330R2J-3-GP  [R402H16]  30.33 7.76 90 top
R6109  100R2J-2-GP  [R402H14]  169.73 166.94 0 bottom
R6110  10KR2J-3-GP  [R402H16]  34.27 7.38 0 top
R6201  1KR2J-1-GP  [R402H16]  162.41 111.8 270 bottom
R6202  0R0402-PAD-2-GP  [0R0402-PAD-1]  160.87 117.08 180 bottom
R6203  10KR2J-3-GP  [R402H16]  163.81 149.49 270 bottom
R6205  0R3J-0-U-GP  [R603H22]  161.68 121.3 0 bottom
R6206  51KR2J-1-GP  [R402H16]  162.26 126.63 180 top
R6207  100KR2J-1-GP  [R402H16]  161.37 126.63 180 top
R6208  100KR2J-1-GP  [R402H16]  164.57 130.44 180 top
R6209  0R3J-0-U-GP  [R603H22]  50.27 77.23 180 top
R6210  0R0402-PAD-2-GP  [0R0402-PAD-1]  55.86 79 90 top
R6211  0R0402-PAD-2-GP  [0R0402-PAD-1]  55.86 78.12 90 top
R6212  0R0402-PAD-2-GP  [0R0402-PAD-1]  57.13 75.19 90 top
R6213  0R0402-PAD-2-GP  [0R0402-PAD-1]  57.13 74.31 90 top
R6214  100R3J-4-GP  [R603H22]  164.19 152.28 0 bottom
R6215  0R2J-2-GP  [R402H16]  166.68 144.97 270 bottom
R6216  0R3J-0-U-GP  [R603H22]  166.61 146.95 90 bottom
R6217  0R2J-2-GP  [R402H16]  166.66 145.83 270 bottom
R6218  20KR2F-L-GP  [R402H16]  170.06 149.52 0 bottom
R6301  0R2J-2-GP  [R402H16]  162.41 36.21 90 top
R6302  0R2J-2-GP  [R402H16]  163.3 30.87 90 top
R6305  0R3J-0-U-GP  [R603H22]  167.62 21.47 270 bottom
R6501  0R2J-2-GP  [R402H16]  146.54 143.37 270 top
R6502  0R2J-2-GP  [R402H16]  152.13 138.8 90 top
RJ45  RJ45-8P-184-GP  [C100PF-10809-L]  6.4 170.97 90 bottom
RN401  SRN2K2J-1-GP  [ARES2H16]  159.62 123.96 180 top
RN402  SRN4K7J-8-GP  [SMD-ARES4H18]  94.47 91.83 90 top
RN404  SRN1KJ-4-GP  [ARES8-CN24H20]  86.24 73.59 270 bottom
RN405  SRN1KJ-4-GP  [ARES8-CN24H20]  83.8 80.78 270 top
RN407  SRN1KJ-4-GP  [ARES8-CN24H20]  89.01 79.26 90 bottom
RN408  SRN1KJ-11-GP-U  [SMD-ARES4-2H18-U]  97.77 92.39 0 bottom
RN601  SRN2K2J-1-GP  [ARES2H16]  139.68 82.18 270 bottom
RN602  SRN100KJ-6-GP  [SMD-ARES4]  145.52 92.02 90 bottom
RN603  SRN10KJ-5-GP  [ARES2H18]  145.01 89.48 0 bottom
RN1901  SRN0J-7-GP-U  [ARES8-CN24H22]  133.08 103.52 270 bottom
RN1902  SRN0J-6-GP  [SMD-ARES4H20]  119.36 93.23 180 top
RN1903  SRN0J-6-GP  [SMD-ARES4H20]  122.16 105.42 0 bottom
RN1904  SRN10KJ-5-GP  [ARES2H18]  137.78 98.05 90 top
RN2401  SRN4K7J-8-GP  [SMD-ARES4H18]  121.04 155.84 270 top
RN2501  SRN10KJ-5-GP  [ARES2H18]  143.34 101.38 180 top
RN2601  SRN0J-6-GP  [SMD-ARES4H20]  75.67 67.57 180 top
RN2602  SRN2K2J-1-GP  [ARES2H16]  75.67 67.57 0 bottom
RN2901  SRN2K2J-1-GP  [ARES2H16]  160.38 23.12 270 bottom
RN3001  SRN10KJ-5-GP  [ARES2H18]  61.83 168.54 180 top
RN3101  SRN75J-1-GP  [ARES8-CN24H22]  21.83 177.18 180 bottom
RN4301  SRN100J-4-GP  [ARES8-CN24H20]  148.57 174.64 270 top
RN5201  SRN100J-4-GP  [ARES8-CN24H20]  100.44 147.33 90 bottom
RN5203  SRN100KJ-5-GP  [ARES8-CN24H20]  102.6 151.14 270 bottom
RN5204  SRN33J-5-GP-U  [SMD-ARES4H18]  97.64 142.86 90 bottom
RN5401  SRN2K2J-1-GP  [ARES2H16]  29.75 79.61 90 bottom
RN5402  SRN499F-GP  [ARES8-CN24H20]  22.46 72.65 90 top
RN5403  SRN499F-GP  [ARES8-CN24H20]  22.46 76.21 90 top
RN5404  SRN2K2J-1-GP  [ARES2H16]  21.7 79.72 270 bottom
RN5506  SRN33J-5-GP-U  [SMD-ARES4H18]  26.27 72.15 90 top
RN5507  SRN33J-5-GP-U  [SMD-ARES4H18]  26.27 72.15 270 bottom
RN5508  SRN2K2J-1-GP  [ARES2H16]  30.23 67.8 0 bottom
RN5509  SRN4K7J-8-GP  [SMD-ARES4H18]  33.07 64.69 0 bottom
RN5601  SRN10KJ-5-GP  [ARES2H18]  162.92 83.45 90 top
RN6201  SRN4K7J-8-GP  [SMD-ARES4H18]  48.88 74.94 90 top
RN6203  SRN10KJ-5-GP  [ARES2H18]  51.16 79.51 270 top
RN6501  SRN0J-7-GP-U  [ARES8-CN24H22]  143.75 140.47 180 top
RN6502  SRN10KJ-6-GP  [ARES8-CN24-MUH20]  89.01 82.18 270 bottom
RTC1  BAT-060003HA002M213ZL-GP-U1  [060003HA002M213ZL-U2]  41.3 13.77 0 bottom
SPI25  W25Q64FVSSIQ-GP  [SOIC8-1H86]  144.53 105.17 270 bottom
SPK1  ACES-CON4-29-GP  [50224-0040N-001]  70 7.22 90 bottom
SPR1  SPRING-31-GP-U  [SPR6035H166]  85.3 58.77 270 top
SPR2  SPRING-102-GP  [SPR5930H154]  69.3 82.02 0 bottom
SPR3  SPRING-13-GP-U  [SPR7837H229]  150.9 34.27 0 bottom
SPR4  SPRING-7-GP  [SPR6438H83]  167.2 145.47 180 top
SSKT2  SKT-G6179HT0321-001-GP  [G6179HT0321-001]  144.51 105.17 90 bottom
TC3501  SC100U6D3V6MX-GP  [C1206H71]  22.26 43.32 0 top
TC4501  SE220U6D3VM-30-GP  [SE361416H178]  33.26 31.25 270 bottom
TC4503  SE220U6D3VM-30-GP  [SE361416H178]  44.56 31.13 90 bottom
THM26  W83L771AWG-2-GP  [MSOP8-1H44]  76 58.46 0 top
TP401  TPAD14-OP-GP  [TPAD14-OP]  110.9 82.17 0 top
TP402  TPAD14-OP-GP  [TPAD14-OP]  110.64 80.85 0 top
TP403  TPAD14-OP-GP  [TPAD14-OP]  107.26 83.39 0 top
TP404  TPAD14-OP-GP  [TPAD14-OP]  102.95 81.67 180 bottom
TP409  TPAD14-OP-GP  [TPAD14-OP]  109.42 78.84 0 top
TP410  TPAD14-OP-GP  [TPAD14-OP]  128.09 77.93 0 top
TP411  TPAD14-OP-GP  [TPAD14-OP]  126.82 77.93 0 top
TP416  TPAD14-OP-GP  [TPAD14-OP]  122.41 93.81 0 top
TP417  TPAD14-OP-GP  [TPAD14-OP]  121.14 93.36 0 top
TP418  TPAD14-OP-GP  [TPAD14-OP]  114.92 79.34 0 top
TP420  TPAD14-OP-GP  [TPAD14-OP]  113.36 79.32 0 top
TP421  TPAD14-OP-GP  [TPAD14-OP]  125.43 81.1 0 top
TP422  TPAD14-OP-GP  [TPAD14-OP]  128.2 79.74 0 top
TP423  TPAD14-OP-GP  [TPAD14-OP]  125.84 78.98 0 top
TP433  TPAD14-OP-GP  [TPAD14-OP]  108.53 85.55 0 top
TP434  TPAD14-OP-GP  [TPAD14-OP]  107.3 84.85 0 top
TP1901  TPAD14-OP-GP  [TPAD14-OP]  130.63 100.41 180 bottom
TP1903  TPAD14-OP-GP  [TPAD14-OP]  127.06 100.42 180 bottom
TP1904  TPAD14-OP-GP  [TPAD14-OP]  125.43 94.69 0 top
TP2401  TPAD14-OP-GP  [TPAD14-OP]  153.68 129.17 270 top
TP2402  TPAD14-OP-GP  [TPAD14-OP]  146.29 130.69 270 top
TP2702  TPAD14-OP-GP  [TPAD14-OP]  150.73 8.49 270 bottom
TP3001  TPAD14-OP-GP  [TPAD14-OP]  52.12 175.12 0 top
TP3002  TPAD14-OP-GP  [TPAD14-OP]  52.17 176.78 180 top
TP3003  TPAD14-OP-GP  [TPAD14-OP]  51.16 173.11 180 top
TP3201  TPAD14-OP-GP  [TPAD14-OP]  22.84 19.06 180 bottom
TP5801  TPAD14-OP-GP  [TPAD14-OP]  163.18 47.89 0 top
TP5802  TPAD14-OP-GP  [TPAD14-OP]  168.64 51.95 0 top
TP5803  TPAD14-OP-GP  [TPAD14-OP]  165.72 48.78 0 top
TP5804  TPAD14-OP-GP  [TPAD14-OP]  169.15 55.13 0 top
TPAD1  ACES-CON8-40-GP  [50505-0084N-002]  66.3 77.27 90 top
TR3401  COIL-35OHM-GP  [L125100-4P-1H37]  25.13 40.78 0 bottom
TR3402  COIL-35OHM-GP  [L125100-4P-1H37]  25.38 38.62 0 bottom
TR3404  FILTER-4P-137-GP-U  [L125100-4P-4H28]  22.03 36.1 180 top
TR3405  FILTER-4P-137-GP-U  [L125100-4P-4H28]  154.54 45.35 0 bottom
TR3406  FILTER-4P-137-GP-U  [L125100-4P-4H28]  154.54 41.41 0 bottom
TR5209  FILTER-4P-137-GP-U  [L125100-4P-4H28]  97.64 141.62 180 top
TR5801  FILTER-4P-137-GP-U  [L125100-4P-4H28]  160.51 66.97 90 bottom
U402  NC7WV07P6X-GP  [SC70-6H44]  94.34 93.23 90 bottom
U701  AP2138N-1D5TRG1-GP  [SOT23-2D8-312H58]  148.95 94.63 180 bottom
U3101  TVWDF1004AD0-1-GP  [DFN10G2510H26]  37.19 173.49 270 bottom
U3102  TVWDF1004AD0-1-GP  [DFN10G2510H26]  36.56 173.62 270 top
U3201  RTS5170-GR-GP  [QFN24-G2D5H40-U]  18.14 19.95 270 bottom
U3402  AZ1045-04F-R7G-GP  [DFN10G2510H26]  19.39 39.91 270 bottom
U3503  G524B2T11U-GP  [SOT-23-5H58]  157.97 29.47 0 bottom
U3504  G524B2T11U-GP  [SOT-23-5H58]  25.51 69.07 90 bottom
U3601  G5016KD1U-GP  [DFN14J3020-G255D85H32]  39.02 18.58 0 top
